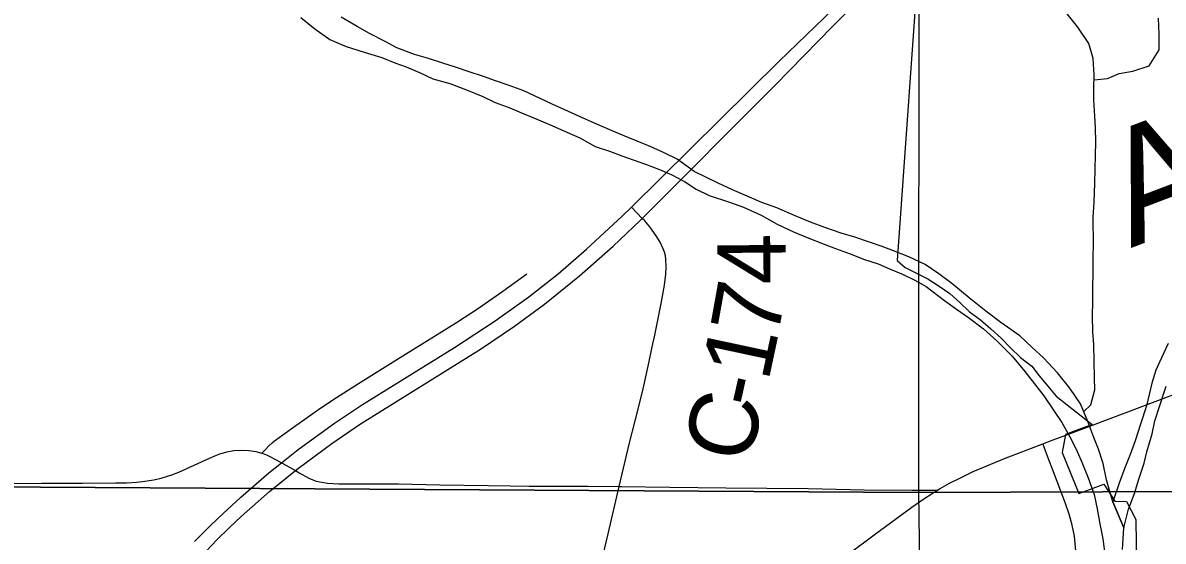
# Model space of a CAD drawing. Extents: x 0 to 34, y 0 to 22.
# Drawn here: x 7.165 to 8.111, y 19.232 to 19.661 of the extents above; entities that cross this region are included whole.
import ezdxf

# ---------------------------------------------------------------- set-up
doc = ezdxf.new("R2010")
doc.units = 0
for name, color, linetype in [('GM_X_County_Road', 7, 'Continuous'), ('GM_X_County_Road_Text', 7, 'Continuous'), ('GM_X_Major_River', 7, 'Continuous'), ('GM_X_Minor_River', 7, 'Continuous'), ('GM_X_Minor_River_Text', 7, 'Continuous'), ('GM_X_Section', 7, 'Continuous'), ('GM_X_State_Route', 7, 'Continuous'), ('GM_X_Township_Road', 7, 'Continuous'), ('GM_X_Unincorporated', 7, 'Continuous')]:
    doc.layers.add(name, color=color, linetype=linetype)

msp = doc.modelspace()

# ---------------------------------------------------------------- linework, layer by layer
at = {"layer": 'GM_X_County_Road'}
for p, q in [((8.05217, 19.32804), (8.11907, 19.353)), ((8.03013, 19.31972), (8.05217, 19.32804))]:
    msp.add_line(p, q, dxfattribs=at)
for points in [[(7.67872, 19.49935), (7.67429, 19.50389), (7.66971, 19.50858)], [(7.68753, 19.39546), (7.68874, 19.40131), (7.69443, 19.42879), (7.69715, 19.44404), (7.69832, 19.45313), (7.69863, 19.45928), (7.69834, 19.46541), (7.6979, 19.46842), (7.69721, 19.47135), (7.69618, 19.47417), (7.69344, 19.47966), (7.69029, 19.48495), (7.68486, 19.49248), (7.68074, 19.49728), (7.67872, 19.49935)], [(7.65951, 19.27714), (7.66818, 19.31339), (7.67292, 19.33149), (7.67891, 19.35567), (7.6837, 19.37692), (7.68753, 19.39546)], [(8.01097, 19.31262), (8.0197, 19.31583), (8.03013, 19.31972)], [(7.15552, 19.27975), (7.18017, 19.28003), (7.21432, 19.27998), (7.24151, 19.28023), (7.25071, 19.28032), (7.25515, 19.28056), (7.25905, 19.28078), (7.26409, 19.28127), (7.27333, 19.28281), (7.27942, 19.28419), (7.28836, 19.28679), (7.29415, 19.28904), (7.31951, 19.30075), (7.32545, 19.30318), (7.32814, 19.30412), (7.33118, 19.30518), (7.33391, 19.30599), (7.33991, 19.30704), (7.34601, 19.30737), (7.35211, 19.30703), (7.35816, 19.30605), (7.36308, 19.30474)], [(7.36308, 19.30474), (7.36405, 19.30448), (7.36688, 19.30341), (7.36961, 19.3021), (7.37502, 19.29918), (7.37943, 19.2968)], [(7.92362, 19.27405), (7.92603, 19.27553), (7.93367, 19.27989), (7.94285, 19.28445), (7.95335, 19.28957), (7.97914, 19.30023), (8.01097, 19.31262)], [(7.37943, 19.2968), (7.38053, 19.2962), (7.39092, 19.29033), (7.39406, 19.28855), (7.40212, 19.28398), (7.4054, 19.28269), (7.40808, 19.28162), (7.41118, 19.28091), (7.41742, 19.28001), (7.42681, 19.27948), (7.45118, 19.27945), (7.47653, 19.27942), (7.51068, 19.27862), (7.55086, 19.27794), (7.56935, 19.2776), (7.58476, 19.27736), (7.59686, 19.27734), (7.60291, 19.27734), (7.63385, 19.27736), (7.65951, 19.27714)], [(7.61596, 19.07986), (7.61634, 19.08595), (7.61673, 19.09225), (7.61814, 19.10156), (7.62132, 19.11684), (7.62769, 19.14418), (7.63728, 19.18355), (7.65046, 19.23785), (7.65951, 19.27714)], [(7.65951, 19.27714), (7.66155, 19.27717), (7.70152, 19.27659), (7.74792, 19.27609), (7.78211, 19.27581), (7.81627, 19.2754), (7.8627, 19.27428), (7.90264, 19.274), (7.91497, 19.27408), (7.92362, 19.27405)], [(7.8493, 19.2208), (7.87219, 19.23783), (7.90225, 19.25991), (7.91163, 19.26642), (7.92009, 19.2719), (7.92362, 19.27405)]]:
    msp.add_lwpolyline(points, dxfattribs=at)
at = {"layer": 'GM_X_Major_River'}
for points in [[(7.39547, 19.66594), (7.4069, 19.65654), (7.41946, 19.64753), (7.43313, 19.64195), (7.44793, 19.63713), (7.46274, 19.63269), (7.47337, 19.62822), (7.48286, 19.62488), (7.49388, 19.62041), (7.5049, 19.61518), (7.51894, 19.61112), (7.53299, 19.60591), (7.54628, 19.60032), (7.55654, 19.59547), (7.56869, 19.59101), (7.57857, 19.58691), (7.5892, 19.58244), (7.60173, 19.57723), (7.61617, 19.57089), (7.62681, 19.56604), (7.63973, 19.55893), (7.6515, 19.55523), (7.66175, 19.55113), (7.67125, 19.54779), (7.68149, 19.54446), (7.69289, 19.53999), (7.70314, 19.53552), (7.71379, 19.52991), (7.7233, 19.52353), (7.73432, 19.51831), (7.75102, 19.51274), (7.76279, 19.50866), (7.77723, 19.50194), (7.79054, 19.49446), (7.80421, 19.48811), (7.81561, 19.48365), (7.82966, 19.47807), (7.83915, 19.47434), (7.8513, 19.46989), (7.86307, 19.46542), (7.87446, 19.46171), (7.88396, 19.45761), (7.89459, 19.45314), (7.90485, 19.44829), (7.91436, 19.44305), (7.92959, 19.43141), (7.93948, 19.42428), (7.94938, 19.41715), (7.96194, 19.40776), (7.97299, 19.39798), (7.98558, 19.38519), (7.99628, 19.37237), (8.0043, 19.36219), (8.01194, 19.35239), (8.01998, 19.34031), (8.02686, 19.33013), (8.03338, 19.31842), (8.03875, 19.30822), (8.04338, 19.29726), (8.04877, 19.2844), (8.05379, 19.27041), (8.05614, 19.25867), (8.0585, 19.24617), (8.06086, 19.23368), (8.06246, 19.22117)], [(8.06918, 19.26441), (8.06393, 19.28262), (8.06118, 19.29625), (8.05732, 19.30798), (8.05346, 19.31781), (8.04845, 19.33105), (8.04228, 19.34579), (8.03348, 19.35862), (8.02317, 19.37144), (8.01172, 19.38386), (8.00182, 19.39251), (7.9919, 19.40192), (7.9763, 19.41318), (7.96374, 19.42257), (7.95003, 19.43346), (7.93555, 19.44549), (7.92489, 19.45337), (7.91348, 19.46125), (7.8998, 19.4676), (7.88727, 19.47243), (7.87777, 19.47615), (7.86638, 19.47986), (7.85499, 19.48394), (7.84361, 19.48727), (7.83032, 19.49172), (7.81817, 19.49618), (7.80564, 19.5014), (7.79044, 19.50811), (7.77791, 19.51257), (7.7536, 19.523), (7.74182, 19.5286), (7.73156, 19.53346), (7.72168, 19.53831), (7.7076, 19.54844), (7.69696, 19.55367), (7.68518, 19.55889), (7.67455, 19.56336), (7.66429, 19.56746), (7.65176, 19.57268), (7.64112, 19.57753), (7.62973, 19.58237), (7.61757, 19.58797), (7.60389, 19.59393), (7.59401, 19.59879), (7.58033, 19.60513), (7.56818, 19.60959), (7.5568, 19.6133), (7.54692, 19.61702), (7.53516, 19.62072), (7.52453, 19.62443), (7.51314, 19.62814), (7.50137, 19.63184), (7.48961, 19.63517), (7.47518, 19.64075), (7.4653, 19.64598), (7.45237, 19.65271), (7.44211, 19.65832), (7.4288, 19.66619)], [(8.07822, 19.24289), (8.06918, 19.26441)], [(8.0772, 19.22507), (8.07822, 19.24289)]]:
    msp.add_lwpolyline(points, dxfattribs=at)
at = {"layer": 'GM_X_Minor_River'}
msp.add_line((8.06918, 19.26441), (8.07822, 19.24289), dxfattribs=at)
for points in [[(8.04503, 19.33921), (8.051, 19.34472), (8.05432, 19.35726), (8.05388, 19.36711), (8.05378, 19.38115), (8.05331, 19.3948), (8.05248, 19.40541), (8.05239, 19.4183), (8.05268, 19.43082), (8.0526, 19.44182), (8.0529, 19.45433), (8.05281, 19.46761), (8.05312, 19.47747), (8.05296, 19.50022), (8.05363, 19.51274), (8.05428, 19.52868), (8.05458, 19.54005), (8.05488, 19.55181), (8.05518, 19.56244), (8.05472, 19.57457), (8.05428, 19.58404), (8.05343, 19.59731), (8.05335, 19.60793), (8.05366, 19.61817), (8.05281, 19.63182), (8.04932, 19.64431), (8.04013, 19.65789), (8.02791, 19.67297)], [(8.05354, 19.61423), (8.06467, 19.61522), (8.07449, 19.61947), (8.08583, 19.62145), (8.09944, 19.62572), (8.10768, 19.63906), (8.10759, 19.65195), (8.10712, 19.66522)], [(8.11504, 19.39564), (8.10944, 19.38384), (8.10496, 19.37357), (8.10163, 19.36292), (8.09721, 19.34393), (8.09202, 19.32872), (8.08757, 19.31503), (8.08348, 19.30363), (8.07901, 19.29259), (8.07455, 19.28004), (8.06918, 19.26441)], [(8.07822, 19.24289), (8.08228, 19.25849), (8.08711, 19.27142), (8.09082, 19.2832), (8.09527, 19.29651), (8.09748, 19.30601), (8.10192, 19.32083), (8.10412, 19.33146), (8.1082, 19.34439), (8.11339, 19.36036)]]:
    msp.add_lwpolyline(points, dxfattribs=at)
at = {"layer": 'GM_X_Section'}
for points in [[(7.90836, 20.28708), (7.90787, 19.27209), (6.90571, 19.27835), (6.88877, 20.29172)], [(6.90571, 19.27835), (7.90787, 19.27209), (7.92171, 18.27008), (6.91054, 18.26226)]]:
    msp.add_lwpolyline(points, close=True, dxfattribs=at)
at = {"layer": 'GM_X_State_Route'}
for points in [[(7.30448, 19.21033), (7.32582, 19.23296), (7.33591, 19.24294), (7.346, 19.25236), (7.36936, 19.27289), (7.39092, 19.29033), (7.39352, 19.29247), (7.42101, 19.31282), (7.44416, 19.32855), (7.54437, 19.39093), (7.57269, 19.40997), (7.59763, 19.4284), (7.62655, 19.45185), (7.65449, 19.47646), (7.67704, 19.49776), (7.67872, 19.49935), (7.7891, 19.60969), (7.83682, 19.65863), (7.90942, 19.73217)], [(7.90921, 19.73272), (7.89011, 19.46459), (7.89696, 19.45856), (7.90683, 19.45368), (7.91557, 19.44918), (7.92507, 19.44316), (7.93381, 19.43714), (7.94218, 19.4296), (7.95018, 19.42206), (7.95931, 19.41528), (7.96806, 19.40775), (7.97643, 19.40021), (7.98405, 19.39228), (7.99243, 19.38398), (8.00194, 19.37683), (8.00804, 19.3689), (8.01529, 19.36021), (8.02215, 19.35191), (8.05196, 19.32859), (8.02992, 19.32027), (8.02703, 19.30545), (8.04097, 19.27131), (8.06169, 19.27908), (8.07084, 19.26487), (8.08059, 19.26473), (8.08837, 19.2499), (8.08968, 19.14892)], [(7.30729, 19.2316), (7.32045, 19.24476), (7.33064, 19.25446), (7.34548, 19.26825), (7.36892, 19.28851), (7.37943, 19.2968), (7.3932, 19.30774), (7.42322, 19.32969), (7.44645, 19.3451), (7.52299, 19.39236), (7.55678, 19.41443), (7.58455, 19.43434), (7.60902, 19.45347), (7.63253, 19.47375), (7.66215, 19.50117), (7.66971, 19.50858), (7.79243, 19.62975), (7.83707, 19.67289)]]:
    msp.add_lwpolyline(points, dxfattribs=at)
at = {"layer": 'GM_X_Township_Road'}
for points in [[(7.36308, 19.30474), (7.36584, 19.30761), (7.36879, 19.31073), (7.37155, 19.31324), (7.37354, 19.31505), (7.37537, 19.31649), (7.38919, 19.32635), (7.41209, 19.34236), (7.42488, 19.35101), (7.44312, 19.36261), (7.47206, 19.38048), (7.52462, 19.41306), (7.54275, 19.42486), (7.56294, 19.43905), (7.57795, 19.44988), (7.58285, 19.45356)], [(7.98897, 19.11835), (7.99532, 19.12662), (8.0104, 19.1464), (8.01767, 19.15649), (8.0228, 19.16429), (8.02592, 19.16968), (8.0287, 19.17524), (8.03106, 19.18099), (8.03392, 19.18988), (8.03618, 19.19894), (8.03718, 19.20508), (8.03808, 19.21438), (8.03838, 19.2237), (8.03804, 19.22992), (8.03725, 19.23609), (8.03538, 19.24524), (8.03297, 19.25426), (8.03001, 19.26311), (8.01992, 19.28923), (8.01532, 19.30136), (8.01215, 19.30972), (8.01097, 19.31262)]]:
    msp.add_lwpolyline(points, dxfattribs=at)
at = {"layer": 'GM_X_Unincorporated'}
for points in [[(8.9, 19.27567), (8.9, 20.28618), (7.90836, 20.28708), (7.90787, 19.27209)], [(8.9, 18.27692), (8.9, 19.27567), (7.90787, 19.27209), (7.92171, 18.27008)]]:
    msp.add_lwpolyline(points, close=True, dxfattribs=at)

# ---------------------------------------------------------------- texts
at = {"layer": 'GM_X_County_Road_Text'}
for s, rotation, p in [('4', 90.48034, (7.79799, 19.44476)), ('7', 79.76793, (7.79084, 19.39904)), ('1', 77.95615, (7.78321, 19.36316)), ('-', 77.33709, (7.778, 19.33994)), ('C', 77.23235, (7.76774, 19.29466))]:
    msp.add_text(s, height=0.05682, rotation=rotation, dxfattribs=at).set_placement(p)
at = {"layer": 'GM_X_Minor_River_Text'}
msp.add_text('Apple', height=0.094723, rotation=20.76282, dxfattribs=at).set_placement((8.08404, 19.47471))

doc.saveas('drawing.dxf')
